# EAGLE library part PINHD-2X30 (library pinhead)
PIN HEADER
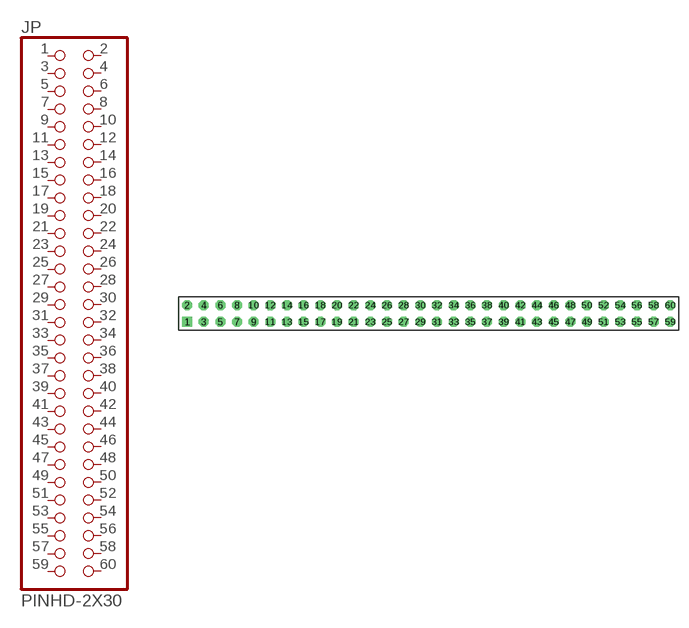
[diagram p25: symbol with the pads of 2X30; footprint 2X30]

Designator prefix JP

## PINHD-2X30  [2X30]
1  1  pas
2  2  pas
3  3  pas
4  4  pas
5  5  pas
6  6  pas
7  7  pas
8  8  pas
9  9  pas
10  10  pas
11  11  pas
12  12  pas
13  13  pas
14  14  pas
15  15  pas
16  16  pas
17  17  pas
18  18  pas
19  19  pas
20  20  pas
21  21  pas
22  22  pas
23  23  pas
24  24  pas
25  25  pas
26  26  pas
27  27  pas
28  28  pas
29  29  pas
30  30  pas
31  31  pas
32  32  pas
33  33  pas
34  34  pas
35  35  pas
36  36  pas
37  37  pas
38  38  pas
39  39  pas
40  40  pas
41  41  pas
42  42  pas
43  43  pas
44  44  pas
45  45  pas
46  46  pas
47  47  pas
48  48  pas
49  49  pas
50  50  pas
51  51  pas
52  52  pas
53  53  pas
54  54  pas
55  55  pas
56  56  pas
57  57  pas
58  58  pas
59  59  pas
60  60  pas

## Footprint 2X30 (pad centres in mm)
PIN HEADER - 0.1"
drill 1.016 square: 1 -38.1,-1.27
drill 1.016 octagon: 2 -38.1,1.27; 3 -35.56,-1.27; 4 -35.56,1.27; 5 -33.02,-1.27; 6 -33.02,1.27; 7 -30.48,-1.27; 8 -30.48,1.27; 9 -27.94,-1.27; 10 -27.94,1.27; 11 -25.4,-1.27; 12 -25.4,1.27; 13 -22.86,-1.27; 14 -22.86,1.27; 15 -20.32,-1.27; 16 -20.32,1.27; 17 -17.78,-1.27; 18 -17.78,1.27; 19 -15.24,-1.27; 20 -15.24,1.27; 21 -12.7,-1.27; 22 -12.7,1.27; 23 -10.16,-1.27; 24 -10.16,1.27; 25 -7.62,-1.27; 26 -7.62,1.27; 27 -5.08,-1.27; 28 -5.08,1.27; 29 -2.54,-1.27; 30 -2.54,1.27; 31 0,-1.27; 32 0,1.27; 33 2.54,-1.27; 34 2.54,1.27; 35 5.08,-1.27; 36 5.08,1.27; 37 7.62,-1.27; 38 7.62,1.27; 39 10.16,-1.27; 40 10.16,1.27; 41 12.7,-1.27; 42 12.7,1.27; 43 15.24,-1.27; 44 15.24,1.27; 45 17.78,-1.27; 46 17.78,1.27; 47 20.32,-1.27; 48 20.32,1.27; 49 22.86,-1.27; 50 22.86,1.27; 51 25.4,-1.27; 52 25.4,1.27; 53 27.94,-1.27; 54 27.94,1.27; 55 30.48,-1.27; 56 30.48,1.27; 57 33.02,-1.27; 58 33.02,1.27; 59 35.56,-1.27; 60 35.56,1.27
